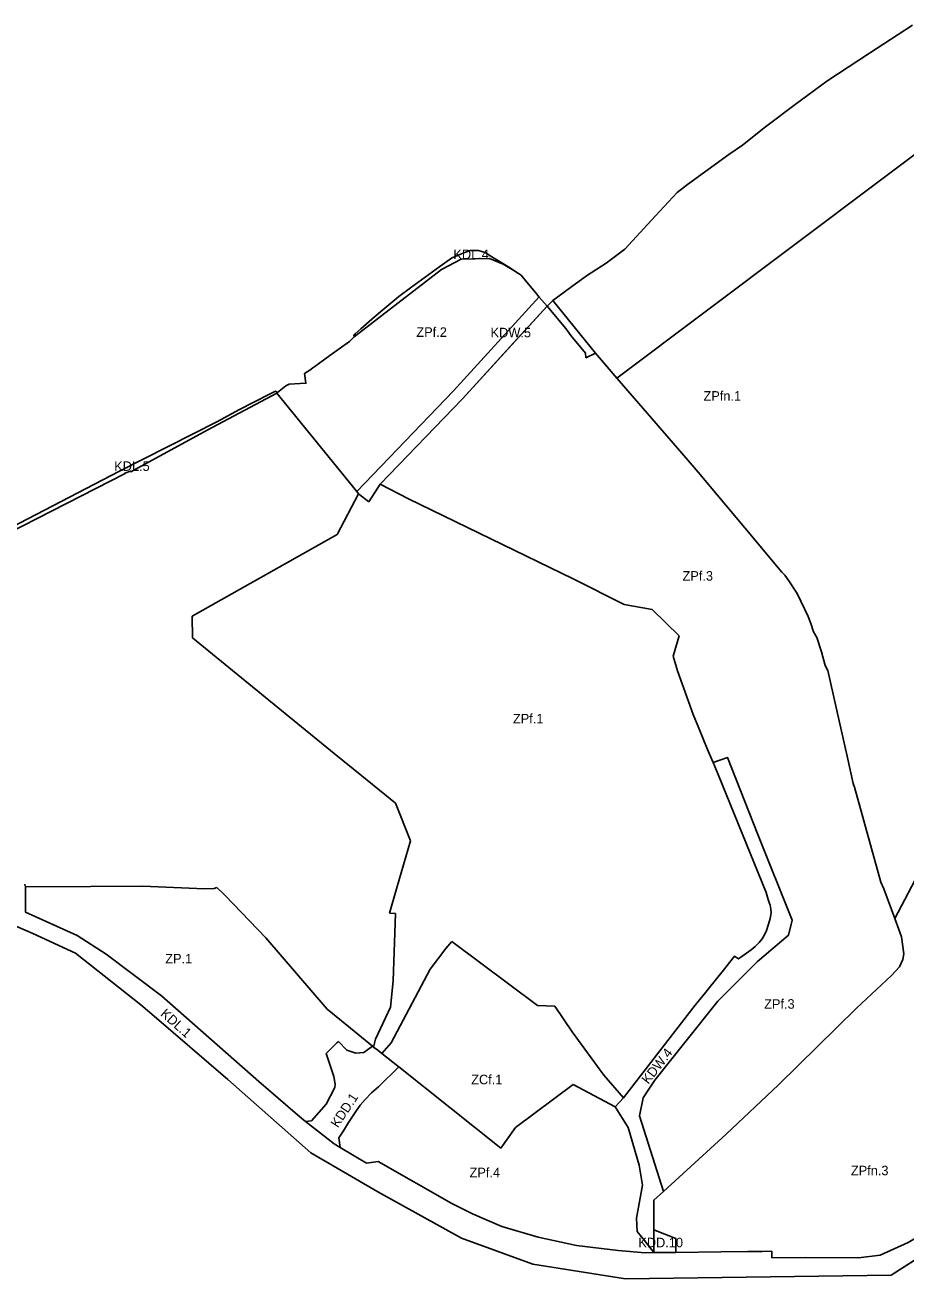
# Model space of a CAD drawing. Extents: x 7432050 to 7433361, y 5551438 to 5552391.
# Drawn here: x 7432263 to 7432632, y 5551602 to 5552127 of the extents above; entities that cross this region are included whole.
import ezdxf

# ---------------------------------------------------------------- set-up
doc = ezdxf.new("R2010")
doc.units = 0
for name, color, linetype in [('granica planu', 7, 'Continuous'), ('linie rozgraniczające', 7, 'Continuous'), ('MPZP_Niebyla_Na_Wzgorzach', 7, 'Continuous'), ('oznaczenia przeznaczen', 7, 'Continuous')]:
    doc.layers.add(name, color=color, linetype=linetype)

msp = doc.modelspace()

# ---------------------------------------------------------------- linework, layer by layer
at = {"layer": 'granica planu'}
for p, q in [((7432347.63, 5551685.25), (7432316.68, 5551711.87)), ((7432382.47, 5551654.43), (7432347.63, 5551685.25))]:
    msp.add_line(p, q, dxfattribs=at)
for points in [[(7432221.7, 5551898.54), (7432302.19, 5551940.32), (7432343.33, 5551961.11), (7432352.2, 5551966.03), (7432365.11, 5551972.59), (7432367.59, 5551973.86), (7432368.45, 5551973.3), (7432371.98, 5551976.08), (7432373.31, 5551976.79), (7432377.93, 5551977.13), (7432380.37, 5551977.17), (7432379.72, 5551981.26), (7432381.95, 5551982.71), (7432383.23, 5551983.62), (7432384.14, 5551984.25), (7432390.4, 5551988.89), (7432394.29, 5551991.66), (7432398.69, 5551994.64), (7432400.53, 5551996.66), (7432400.5, 5551997.26), (7432401.01, 5551997.86), (7432403.46, 5551999.98), (7432408.05, 5552004.09), (7432410.71, 5552006.28), (7432411.75, 5552007.24), (7432419.32, 5552013.56), (7432424.23, 5552017.22), (7432436.48, 5552026.22), (7432441.38, 5552029.66), (7432444.19, 5552030.86), (7432446.95, 5552032.05), (7432449.3, 5552032.83), (7432449.9, 5552032.86), (7432452.78, 5552032.87), (7432455.5, 5552032.02), (7432458.27, 5552030.27), (7432461.07, 5552028.59), (7432463.67, 5552027.06), (7432466.08, 5552025.5), (7432468.32, 5552023.95), (7432470.55, 5552022.58), (7432473, 5552019.6), (7432476.6, 5552015.27), (7432478.22, 5552013.26), (7432481.49, 5552009.51), (7432483.91, 5552011.83), (7432491.35, 5552017.28), (7432498.04, 5552022.19), (7432506.23, 5552027.6), (7432514.12, 5552033.45), (7432526.98, 5552047.45), (7432536.03, 5552057.22), (7432540.38, 5552060.47), (7432557.62, 5552073.18), (7432563.45, 5552077.06), (7432573.11, 5552084.76), (7432585.54, 5552094.03), (7432598.75, 5552103.85), (7432616.71, 5552115.62), (7432634.66, 5552127.39)], [(7432265.87, 5551746.41), (7432259.5, 5551749.3), (7432229, 5551754.7), (7432185.43, 5551755.05)], [(7432316.68, 5551711.87), (7432311.21, 5551716.58), (7432283.77, 5551738.28), (7432265.87, 5551746.41)], [(7432625.82, 5551603.17), (7432514.43, 5551601.62), (7432475.52, 5551607.83), (7432445.65, 5551618.75), (7432410.53, 5551638.1), (7432382.47, 5551654.43)], [(7432690.81, 5551642.54), (7432672.61, 5551633.22), (7432625.82, 5551603.17)]]:
    msp.add_lwpolyline(points, dxfattribs=at)
at = {"layer": 'linie rozgraniczające'}
for p, q in [((7432634.66, 5552127.39), (7432616.71, 5552115.62)), ((7432616.71, 5552115.62), (7432598.75, 5552103.85)), ((7432598.75, 5552103.85), (7432585.54, 5552094.03)), ((7432540.38, 5552060.47), (7432536.03, 5552057.22)), ((7432457.33, 5552029.47), (7432463.06, 5552027.2)), ((7432463.06, 5552027.2), (7432468.23, 5552024.01)), ((7432470.55, 5552022.58), (7432468.32, 5552023.95)), ((7432498.04, 5552022.19), (7432491.35, 5552017.28)), ((7432491.35, 5552017.28), (7432483.91, 5552011.83)), ((7432483.91, 5552011.83), (7432481.49, 5552009.51)), ((7432445.95, 5551970.65), (7432481.49, 5552009.51)), ((7432489.31, 5552000.22), (7432481.49, 5552009.51)), ((7432481.49, 5552009.51), (7432489.31, 5552000.22)), ((7432491.5, 5551997.28), (7432489.31, 5552000.22)), ((7432489.31, 5552000.22), (7432491.5, 5551997.28)), ((7432497.53, 5551989.86), (7432491.5, 5551997.28)), ((7432491.5, 5551997.28), (7432497.53, 5551989.86)), ((7432497.72, 5551987.81), (7432497.53, 5551989.86)), ((7432497.53, 5551989.86), (7432497.72, 5551987.81)), ((7432501.82, 5551989.76), (7432497.72, 5551987.81)), ((7432497.72, 5551987.81), (7432501.82, 5551989.76)), ((7432511.77, 5551978.2), (7432501.82, 5551989.76)), ((7432501.82, 5551989.76), (7432511.77, 5551978.2)), ((7432525.41, 5551962.4), (7432511.77, 5551978.2)), ((7432511.77, 5551978.2), (7432525.41, 5551962.4)), ((7432368.23, 5551973.08), (7432368.19, 5551973.04)), ((7432368.23, 5551973.08), (7432368.45, 5551973.3)), ((7432411.54, 5551934.85), (7432445.95, 5551970.65)), ((7432445.95, 5551970.65), (7432411.54, 5551934.85)), ((7432540.59, 5551944.84), (7432525.41, 5551962.4)), ((7432525.41, 5551962.4), (7432540.59, 5551944.84)), ((7432544.87, 5551939.89), (7432540.59, 5551944.84)), ((7432540.59, 5551944.84), (7432544.87, 5551939.89)), ((7432564.45, 5551916.63), (7432544.87, 5551939.89)), ((7432544.87, 5551939.89), (7432564.45, 5551916.63)), ((7432401.67, 5551931.79), (7432402.48, 5551930.79)), ((7432406.76, 5551927.42), (7432411.54, 5551934.85)), ((7432411.54, 5551934.85), (7432423.31, 5551928.77)), ((7432393.51, 5551913.74), (7432402.48, 5551930.79)), ((7432402.48, 5551930.79), (7432406.76, 5551927.42)), ((7432423.31, 5551928.77), (7432492.36, 5551895.16)), ((7432579.96, 5551898.02), (7432564.45, 5551916.63)), ((7432564.45, 5551916.63), (7432579.96, 5551898.02)), ((7432332.71, 5551879.57), (7432393.51, 5551913.74)), ((7432492.36, 5551895.16), (7432513.87, 5551884.43)), ((7432581.16, 5551896.77), (7432579.96, 5551898.02)), ((7432579.96, 5551898.02), (7432581.16, 5551896.77)), ((7432582.83, 5551894.41), (7432581.16, 5551896.77)), ((7432581.16, 5551896.77), (7432582.83, 5551894.41)), ((7432586.35, 5551889.02), (7432582.83, 5551894.41)), ((7432582.83, 5551894.41), (7432586.35, 5551889.02)), ((7432513.87, 5551884.43), (7432525.58, 5551882.27)), ((7432587.86, 5551885.89), (7432586.35, 5551889.02)), ((7432586.35, 5551889.02), (7432587.86, 5551885.89)), ((7432590.92, 5551879.35), (7432587.86, 5551885.89)), ((7432587.86, 5551885.89), (7432590.92, 5551879.35)), ((7432332.83, 5551870.48), (7432332.71, 5551879.57)), ((7432525.58, 5551882.27), (7432536.88, 5551871.25)), ((7432592.04, 5551876.49), (7432590.92, 5551879.35)), ((7432590.92, 5551879.35), (7432592.04, 5551876.49)), ((7432593.15, 5551872.94), (7432592.04, 5551876.49)), ((7432592.04, 5551876.49), (7432593.15, 5551872.94)), ((7432392.23, 5551821.99), (7432332.83, 5551870.48)), ((7432536.88, 5551871.25), (7432534.37, 5551862.75)), ((7432594.55, 5551870.58), (7432593.15, 5551872.94)), ((7432593.15, 5551872.94), (7432594.55, 5551870.58)), ((7432596.55, 5551864.52), (7432594.55, 5551870.58)), ((7432594.55, 5551870.58), (7432596.55, 5551864.52)), ((7432598.15, 5551858.91), (7432596.55, 5551864.52)), ((7432596.55, 5551864.52), (7432598.15, 5551858.91)), ((7432534.37, 5551862.75), (7432536.14, 5551856.55)), ((7432599.15, 5551856.76), (7432598.15, 5551858.91)), ((7432598.15, 5551858.91), (7432599.15, 5551856.76)), ((7432536.14, 5551856.55), (7432542.74, 5551838.3)), ((7432604.02, 5551835.62), (7432599.15, 5551856.76)), ((7432599.15, 5551856.76), (7432604.02, 5551835.62)), ((7432542.74, 5551838.3), (7432545.15, 5551832.5)), ((7432545.15, 5551832.5), (7432548.8, 5551823.69)), ((7432607.26, 5551820.77), (7432604.02, 5551835.62)), ((7432604.02, 5551835.62), (7432607.26, 5551820.77)), ((7432403.84, 5551812.51), (7432392.23, 5551821.99)), ((7432548.8, 5551823.69), (7432551.01, 5551818.48)), ((7432551.01, 5551818.48), (7432551.16, 5551818.13)), ((7432609.76, 5551809.39), (7432607.26, 5551820.77)), ((7432607.26, 5551820.77), (7432609.76, 5551809.39)), ((7432417.87, 5551801.06), (7432403.84, 5551812.51)), ((7432610.4, 5551807.81), (7432609.76, 5551809.39)), ((7432609.76, 5551809.39), (7432610.4, 5551807.81)), ((7432621.48, 5551768.06), (7432610.4, 5551807.81)), ((7432610.4, 5551807.81), (7432621.48, 5551768.06)), ((7432424.19, 5551785.39), (7432417.87, 5551801.06)), ((7432418.37, 5551765.24), (7432424.19, 5551785.39)), ((7432627.31, 5551752.71), (7432638.67, 5551774.34)), ((7432638.67, 5551774.34), (7432627.31, 5551752.71)), ((7432262.45, 5551767.16), (7432262.81, 5551766)), ((7432290.07, 5551766.19), (7432262.81, 5551766)), ((7432262.81, 5551766), (7432290.07, 5551766.19)), ((7432311.97, 5551766.26), (7432290.07, 5551766.19)), ((7432290.07, 5551766.19), (7432311.97, 5551766.26)), ((7432337.87, 5551765.16), (7432311.97, 5551766.26)), ((7432311.97, 5551766.26), (7432337.87, 5551765.16)), ((7432341.89, 5551765.31), (7432337.87, 5551765.16)), ((7432337.87, 5551765.16), (7432341.89, 5551765.31)), ((7432342.96, 5551765.78), (7432341.89, 5551765.31)), ((7432341.89, 5551765.31), (7432342.96, 5551765.78)), ((7432345.82, 5551763.16), (7432342.96, 5551765.78)), ((7432342.96, 5551765.78), (7432345.82, 5551763.16)), ((7432415.39, 5551754.99), (7432418.37, 5551765.24)), ((7432622.74, 5551765.13), (7432621.48, 5551768.06)), ((7432621.48, 5551768.06), (7432622.74, 5551765.13)), ((7432627.31, 5551752.71), (7432622.74, 5551765.13)), ((7432622.74, 5551765.13), (7432627.31, 5551752.71)), ((7432346.53, 5551762.36), (7432345.82, 5551763.16)), ((7432345.82, 5551763.16), (7432346.53, 5551762.36)), ((7432363.5, 5551744.62), (7432346.53, 5551762.36)), ((7432346.53, 5551762.36), (7432363.5, 5551744.62)), ((7432417.93, 5551754.81), (7432415.39, 5551754.99)), ((7432416.93, 5551726.56), (7432417.93, 5551754.81)), ((7432630.04, 5551745), (7432627.31, 5551752.71)), ((7432627.31, 5551752.71), (7432630.04, 5551745)), ((7432259.5, 5551749.3), (7432265.87, 5551746.41)), ((7432389.23, 5551714.72), (7432363.5, 5551744.62)), ((7432363.5, 5551744.62), (7432389.23, 5551714.72)), ((7432441.5, 5551743.17), (7432439.01, 5551740.21)), ((7432477.46, 5551716.27), (7432441.5, 5551743.17)), ((7432631.1, 5551737.91), (7432630.04, 5551745)), ((7432630.04, 5551745), (7432631.1, 5551737.91)), ((7432439.01, 5551740.21), (7432432.44, 5551731.56)), ((7432630.69, 5551735.62), (7432631.1, 5551737.91)), ((7432631.1, 5551737.91), (7432630.69, 5551735.62)), ((7432625.94, 5551728.88), (7432629.18, 5551732.54)), ((7432629.18, 5551732.54), (7432625.94, 5551728.88)), ((7432629.18, 5551732.54), (7432630.69, 5551735.62)), ((7432630.69, 5551735.62), (7432629.18, 5551732.54)), ((7432415.8, 5551715.61), (7432416.93, 5551726.56)), ((7432432.44, 5551731.56), (7432416.05, 5551700.57)), ((7432611.26, 5551715.13), (7432625.94, 5551728.88)), ((7432625.94, 5551728.88), (7432611.26, 5551715.13)), ((7432548.05, 5551721.9), (7432543.63, 5551716.37)), ((7432484.73, 5551716.02), (7432477.46, 5551716.27)), ((7432492.05, 5551705.26), (7432484.73, 5551716.02)), ((7432543.63, 5551716.37), (7432513.5, 5551677.59)), ((7432316.68, 5551711.87), (7432347.63, 5551685.25)), ((7432347.63, 5551685.25), (7432316.68, 5551711.87)), ((7432399, 5551706.72), (7432389.23, 5551714.72)), ((7432389.23, 5551714.72), (7432399, 5551706.72)), ((7432409.58, 5551702.15), (7432415.8, 5551715.61)), ((7432578.51, 5551682.94), (7432611.26, 5551715.13)), ((7432611.26, 5551715.13), (7432578.51, 5551682.94)), ((7432408.22, 5551699.16), (7432399, 5551706.72)), ((7432399, 5551706.72), (7432408.22, 5551699.16)), ((7432393.3, 5551700.55), (7432394.07, 5551701.24)), ((7432408.77, 5551698.75), (7432409.58, 5551702.15)), ((7432416.05, 5551700.57), (7432412.18, 5551696.21)), ((7432505.31, 5551687.13), (7432492.05, 5551705.26)), ((7432401.23, 5551696.26), (7432404.65, 5551696.63)), ((7432404.65, 5551696.63), (7432408.22, 5551699.16)), ((7432408.22, 5551699.16), (7432408.77, 5551698.75)), ((7432412.18, 5551696.21), (7432418.72, 5551690.99)), ((7432392.14, 5551686.49), (7432390.86, 5551690.32)), ((7432410.85, 5551682.18), (7432419.31, 5551690.52)), ((7432418.72, 5551690.99), (7432419.31, 5551690.52)), ((7432419.31, 5551690.52), (7432462.1, 5551656.42)), ((7432347.63, 5551685.25), (7432382.47, 5551654.43)), ((7432382.47, 5551654.43), (7432347.63, 5551685.25)), ((7432513.5, 5551677.59), (7432505.31, 5551687.13)), ((7432407.92, 5551679.66), (7432410.85, 5551682.18)), ((7432468.2, 5551665.06), (7432492.45, 5551683.16)), ((7432492.45, 5551683.16), (7432510.09, 5551673.77)), ((7432556.55, 5551662.26), (7432578.51, 5551682.94)), ((7432578.51, 5551682.94), (7432556.55, 5551662.26)), ((7432401.57, 5551672.23), (7432403.15, 5551674.54)), ((7432510.09, 5551673.77), (7432513.5, 5551677.59)), ((7432513.5, 5551677.59), (7432510.09, 5551673.77)), ((7432521.72, 5551677.49), (7432520.29, 5551669.94)), ((7432520.29, 5551669.94), (7432521.72, 5551677.49)), ((7432398.27, 5551667.19), (7432399.64, 5551669.24)), ((7432399.64, 5551669.24), (7432401.57, 5551672.23)), ((7432510.09, 5551673.77), (7432515.47, 5551665.08)), ((7432520.29, 5551669.94), (7432530.24, 5551638.34)), ((7432530.24, 5551638.34), (7432520.29, 5551669.94)), ((7432380.19, 5551667.64), (7432382.73, 5551667.89)), ((7432385.16, 5551663.66), (7432380.19, 5551667.64)), ((7432394.2, 5551660.74), (7432396.11, 5551663.69)), ((7432396.11, 5551663.69), (7432398.27, 5551667.19)), ((7432462.1, 5551656.42), (7432468.2, 5551665.06)), ((7432515.47, 5551665.08), (7432520.13, 5551649.31)), ((7432394.72, 5551656.71), (7432394.2, 5551660.74)), ((7432530.24, 5551638.34), (7432556.55, 5551662.26)), ((7432556.55, 5551662.26), (7432530.24, 5551638.34)), ((7432382.47, 5551654.43), (7432410.53, 5551638.1)), ((7432405.71, 5551650.17), (7432394.72, 5551656.71)), ((7432410.71, 5551650.85), (7432405.71, 5551650.17)), ((7432441.5, 5551633.25), (7432410.71, 5551650.85)), ((7432520.13, 5551649.31), (7432521.43, 5551640.87)), ((7432410.53, 5551638.1), (7432445.65, 5551618.75)), ((7432521.43, 5551640.87), (7432519.04, 5551627.1)), ((7432530.24, 5551638.34), (7432526.25, 5551634.71)), ((7432526.25, 5551634.71), (7432530.24, 5551638.34)), ((7432450.18, 5551628.85), (7432441.5, 5551633.25)), ((7432526.25, 5551634.71), (7432526.27, 5551622.22)), ((7432526.27, 5551622.22), (7432526.25, 5551634.71)), ((7432625.82, 5551603.17), (7432672.61, 5551633.22)), ((7432462.45, 5551623.63), (7432450.18, 5551628.85)), ((7432519.04, 5551627.1), (7432519.27, 5551621.57)), ((7432477.77, 5551619.08), (7432462.45, 5551623.63)), ((7432526.27, 5551622.22), (7432535.43, 5551618.63)), ((7432526.28, 5551612.64), (7432526.27, 5551622.22)), ((7432445.65, 5551618.75), (7432475.52, 5551607.83)), ((7432493.82, 5551615.62), (7432477.77, 5551619.08)), ((7432535.43, 5551618.63), (7432535.46, 5551613.11)), ((7432511.27, 5551613.52), (7432493.82, 5551615.62)), ((7432522.64, 5551612.59), (7432511.27, 5551613.52)), ((7432526.28, 5551612.64), (7432522.64, 5551612.59)), ((7432526.28, 5551612.64), (7432535.47, 5551612.76)), ((7432535.47, 5551612.76), (7432535.46, 5551613.11)), ((7432535.46, 5551613.11), (7432535.47, 5551612.76)), ((7432535.47, 5551612.76), (7432554.29, 5551613)), ((7432571.68, 5551613.17), (7432575.69, 5551613.2)), ((7432575.69, 5551613.2), (7432575.73, 5551610.41)), ((7432612.02, 5551610.41), (7432621.14, 5551611.65)), ((7432575.73, 5551610.41), (7432589.83, 5551610.6)), ((7432589.83, 5551610.6), (7432575.73, 5551610.41)), ((7432589.83, 5551610.6), (7432612.02, 5551610.41))]:
    msp.add_line(p, q, dxfattribs=at)
for points in [[(7432221.7, 5551898.54), (7432302.19, 5551940.32), (7432343.33, 5551961.11), (7432352.2, 5551966.03), (7432365.11, 5551972.59), (7432367.59, 5551973.86), (7432368.45, 5551973.3), (7432371.98, 5551976.08), (7432373.31, 5551976.79), (7432377.93, 5551977.13), (7432380.37, 5551977.17), (7432379.72, 5551981.26), (7432381.95, 5551982.71), (7432383.23, 5551983.62), (7432384.14, 5551984.25), (7432390.4, 5551988.89), (7432394.29, 5551991.66), (7432398.69, 5551994.64), (7432400.53, 5551996.66), (7432400.5, 5551997.26), (7432401.01, 5551997.86), (7432403.46, 5551999.98), (7432408.05, 5552004.09), (7432410.71, 5552006.28), (7432411.75, 5552007.24), (7432419.32, 5552013.56), (7432424.23, 5552017.22), (7432436.48, 5552026.22), (7432441.38, 5552029.66), (7432444.19, 5552030.86), (7432446.95, 5552032.05), (7432449.3, 5552032.83), (7432449.9, 5552032.86), (7432452.78, 5552032.87), (7432455.5, 5552032.02), (7432458.27, 5552030.27), (7432461.07, 5552028.59), (7432463.67, 5552027.06), (7432466.08, 5552025.5), (7432468.32, 5552023.95), (7432470.55, 5552022.58), (7432473, 5552019.6), (7432476.6, 5552015.27), (7432478.22, 5552013.26), (7432481.49, 5552009.51), (7432483.91, 5552011.83), (7432491.35, 5552017.28), (7432498.04, 5552022.19), (7432506.23, 5552027.6), (7432514.12, 5552033.45), (7432526.98, 5552047.45), (7432536.03, 5552057.22), (7432540.38, 5552060.47), (7432557.62, 5552073.18), (7432563.45, 5552077.06), (7432573.11, 5552084.76), (7432585.54, 5552094.03), (7432598.75, 5552103.85), (7432616.71, 5552115.62), (7432634.66, 5552127.39)], [(7432585.54, 5552094.03), (7432573.11, 5552084.76), (7432563.45, 5552077.06)], [(7432563.45, 5552077.06), (7432557.62, 5552073.18), (7432540.38, 5552060.47)], [(7432536.03, 5552057.22), (7432526.98, 5552047.45), (7432514.12, 5552033.45)], [(7432468.23, 5552024.01), (7432466.08, 5552025.5), (7432463.67, 5552027.06), (7432461.07, 5552028.59), (7432458.27, 5552030.27), (7432455.5, 5552032.02), (7432452.78, 5552032.87), (7432449.9, 5552032.86), (7432449.3, 5552032.83), (7432446.95, 5552032.05), (7432444.19, 5552030.86), (7432441.38, 5552029.66), (7432436.48, 5552026.22), (7432424.23, 5552017.22), (7432419.32, 5552013.56), (7432411.75, 5552007.24), (7432410.71, 5552006.28), (7432408.05, 5552004.09), (7432403.46, 5551999.98), (7432401.01, 5551997.86), (7432400.5, 5551997.26), (7432400.53, 5551996.66)], [(7432514.12, 5552033.45), (7432506.23, 5552027.6), (7432498.04, 5552022.19)], [(7432400.53, 5551996.66), (7432437.23, 5552024.93), (7432445.4, 5552029.24), (7432457.33, 5552029.47)], [(7432470.55, 5552022.58), (7432470.55, 5552022.58)], [(7432478.13, 5552013.37), (7432442.3, 5551974.06), (7432401.67, 5551931.79)], [(7432481.49, 5552009.51), (7432478.22, 5552013.26), (7432478.13, 5552013.37)], [(7432481.49, 5552009.51), (7432467.41, 5551994.11), (7432445.95, 5551970.65)], [(7432368.19, 5551973.04), (7432338.93, 5551957.54), (7432306.94, 5551940.06), (7432306.83, 5551940.37), (7432304.45, 5551939.53), (7432304.52, 5551939.35), (7432224.57, 5551898.58), (7432224.5, 5551898.75), (7432222.71, 5551897.92), (7432221.22, 5551897.74), (7432221.28, 5551897.29), (7432142.19, 5551884.42), (7432078.18, 5551874.1)], [(7432402.48, 5551930.79), (7432401.67, 5551931.79), (7432368.23, 5551973.08)], [(7432553.09, 5551718.06), (7432569.77, 5551734.75), (7432582.65, 5551745.74), (7432584.21, 5551752.05), (7432569.88, 5551787.93), (7432557.11, 5551820.28), (7432551.16, 5551818.13), (7432553.27, 5551813.18), (7432573.33, 5551763.61), (7432574.25, 5551760.77), (7432574.65, 5551759.53), (7432575.04, 5551758.28), (7432575.35, 5551756.73), (7432575.39, 5551755.12), (7432575.08, 5551752.81), (7432574.39, 5551750.43), (7432573.47, 5551747.74), (7432572.64, 5551745.92), (7432571.62, 5551744.24), (7432570.34, 5551742.68), (7432568.7, 5551740.98), (7432567.03, 5551739.65), (7432565.13, 5551738.15), (7432561.74, 5551735.83), (7432560.1, 5551736.99), (7432554.83, 5551730.39), (7432549.56, 5551723.79), (7432548.05, 5551721.9)], [(7432551.16, 5551818.13), (7432557.11, 5551820.28), (7432569.88, 5551787.93), (7432584.21, 5551752.05), (7432582.65, 5551745.74), (7432569.77, 5551734.75), (7432553.09, 5551718.06)], [(7432262.81, 5551766), (7432262.81, 5551764.95), (7432262.78, 5551755.45), (7432284.45, 5551745.64), (7432296.61, 5551737.86), (7432319.82, 5551720.37), (7432360.56, 5551684.44), (7432376.78, 5551670.37), (7432380.19, 5551667.64)], [(7432265.87, 5551746.41), (7432259.5, 5551749.3), (7432229, 5551754.7), (7432185.43, 5551755.05)], [(7432265.87, 5551746.41), (7432283.77, 5551738.28), (7432311.21, 5551716.58), (7432316.68, 5551711.87)], [(7432316.68, 5551711.87), (7432311.21, 5551716.58), (7432283.77, 5551738.28), (7432265.87, 5551746.41)], [(7432553.09, 5551718.06), (7432539.84, 5551701.49), (7432526.6, 5551684.92), (7432524.16, 5551681.2), (7432521.72, 5551677.49)], [(7432521.72, 5551677.49), (7432524.16, 5551681.2), (7432526.6, 5551684.92), (7432539.84, 5551701.49), (7432553.09, 5551718.06)], [(7432390.86, 5551690.32), (7432388.86, 5551696.15), (7432393.3, 5551700.55)], [(7432394.07, 5551701.24), (7432397.46, 5551697.6), (7432401.23, 5551696.26)], [(7432412.18, 5551696.21), (7432410.48, 5551697.48), (7432408.77, 5551698.75)], [(7432382.73, 5551667.89), (7432388.83, 5551674.89), (7432392.45, 5551681.82), (7432392.59, 5551683.27), (7432392.14, 5551686.49)], [(7432403.15, 5551674.54), (7432405.17, 5551676.82), (7432407.92, 5551679.66)], [(7432394.72, 5551656.71), (7432392.2, 5551658.21), (7432385.16, 5551663.66)], [(7432625.82, 5551603.17), (7432514.43, 5551601.62), (7432475.52, 5551607.83), (7432445.65, 5551618.75), (7432410.53, 5551638.1), (7432382.47, 5551654.43)], [(7432690.81, 5551642.54), (7432672.61, 5551633.22), (7432625.82, 5551603.17)], [(7432519.27, 5551621.57), (7432522.83, 5551617.03), (7432526.28, 5551612.64)], [(7432535.46, 5551613.11), (7432535.43, 5551618.63), (7432526.27, 5551622.22), (7432526.28, 5551612.64)], [(7432645.84, 5551624.65), (7432632.85, 5551616.9), (7432621.14, 5551611.65), (7432612.02, 5551610.41), (7432589.83, 5551610.6)], [(7432621.14, 5551611.65), (7432632.85, 5551616.9), (7432645.84, 5551624.65)], [(7432554.29, 5551613), (7432535.47, 5551612.76), (7432526.28, 5551612.64)], [(7432575.73, 5551610.41), (7432575.69, 5551613.2), (7432571.68, 5551613.17), (7432565.68, 5551613.1), (7432554.29, 5551613)], [(7432554.29, 5551613), (7432565.68, 5551613.1), (7432571.68, 5551613.17)], [(7432475.52, 5551607.83), (7432514.43, 5551601.62), (7432625.82, 5551603.17)]]:
    msp.add_lwpolyline(points, dxfattribs=at)
at = {"layer": 'MPZP_Niebyla_Na_Wzgorzach'}
msp.add_lwpolyline([(7432697.04, 5552119.23), (7432510.77, 5551979.37), (7432501.82, 5551989.76), (7432483.91, 5552011.83), (7432491.35, 5552017.28), (7432498.04, 5552022.19), (7432506.23, 5552027.6), (7432514.12, 5552033.45), (7432526.98, 5552047.45), (7432536.03, 5552057.22), (7432540.38, 5552060.47), (7432557.62, 5552073.18), (7432563.45, 5552077.06), (7432573.11, 5552084.76), (7432585.54, 5552094.03), (7432598.75, 5552103.85), (7432616.71, 5552115.62), (7432634.66, 5552127.39)], dxfattribs=at)

# ---------------------------------------------------------------- texts
at = {"layer": 'oznaczenia przeznaczen'}
for s, p in [('KDL.4', (7432442.21, 5552029.28)), ('ZPf.2', (7432426.68, 5551996.66)), ('KDW.5', (7432457.8, 5551996.45)), ('ZPfn.1', (7432547.07, 5551969.88)), ('KDL.5', (7432299.99, 5551940.45)), ('ZPf.3', (7432538.27, 5551894.42)), ('ZPf.1', (7432467.17, 5551834.56)), ('ZP.1', (7432321.4, 5551733.91)), ('ZPf.3', (7432572.49, 5551714.92)), ('ZCf.1', (7432449.65, 5551683.23)), ('ZPf.4', (7432448.99, 5551644.25)), ('ZPfn.3', (7432608.87, 5551645.08)), ('KDD.10', (7432519.75, 5551614.88))]:
    msp.add_text(s, height=4, dxfattribs=at).set_placement(p)
for s, rotation, p in [('KDL.1', 318.4401, (7432319.07, 5551712.3)), ('KDW.4', 52.1589, (7432523.96, 5551683)), ('KDD.1', 56.4211, (7432393.77, 5551664.72))]:
    msp.add_text(s, height=4, rotation=rotation, dxfattribs=at).set_placement(p)

doc.saveas('drawing.dxf')
